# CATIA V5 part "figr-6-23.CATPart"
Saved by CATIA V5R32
Part number: Part1
Bounding box of the stored display mesh (mm): x 0 to 150, y -70 to 70, z -150 to 69.968
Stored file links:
  D:\PROJECTS\Project 2022\CATIA V5 6R 2022\Resources\Part Files\c06_catia_v5_6r2022_prt\figr-6-23.CATPart
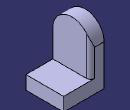
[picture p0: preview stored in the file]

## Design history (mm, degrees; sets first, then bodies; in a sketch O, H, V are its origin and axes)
Body1 (main body)
  Sketch1 on yz-plane, origin (0, 0, 0), H (0, 1, 0), V (0, 0, 1)
    arc A1 centre (0, 0) radius 70 from (70, 0) to (-70, 0) ccw
    point P1 (70, 0)
    point P2 (-70, 0)
    line L1 (-70, 0) -> (-70, -150)
    line L2 (-70, -150) -> (70, -150)
    line L3 (70, -150) -> (70, 0)
    construction circle A2 centre (0, 0) radius 37.5
    radius A1 = 70
    radius A2 = 37.5
    distance O L2 = 150
    coincidence: P1 H, P2 H
    tangency: L1 A1, L3 A1
    horizontal: L2 H
  Pad1: profile Sketch1, direction (1, 0, 0), length 50
  Sketch2 on face of Pad1, origin (50, 0, 0), H (0, 1, 0), V (0, 0, 1)
    line L1 (-70, -150) -> (70, -150)
    line L2 (70, -150) -> (70, -100)
    line L3 (70, -100) -> (-70, -100)
    line L4 (-70, -100) -> (-70, -150)
    reference projected line E1 (-70, -150) -> (70, -150) from edge [face of Pad1 | face of Pad1]
    reference projected line E2 (-70, 0) -> (-70, -150) from edge [face of Pad1 | face of Pad1]
    reference projected line E3 (70, -150) -> (70, 0) from edge [face of Pad1 | face of Pad1]
    length L2 = 50
    horizontal: L1 H, L3 H
    vertical: L2 V, L4 V
    coincidence: L1 E1, E2 L4, L2 E3
  Pad2: profile Sketch2, direction (1, 0, 0), length 100
  Fillet1: radius 15, on edge [face of Pad2 | end face of Pad1]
